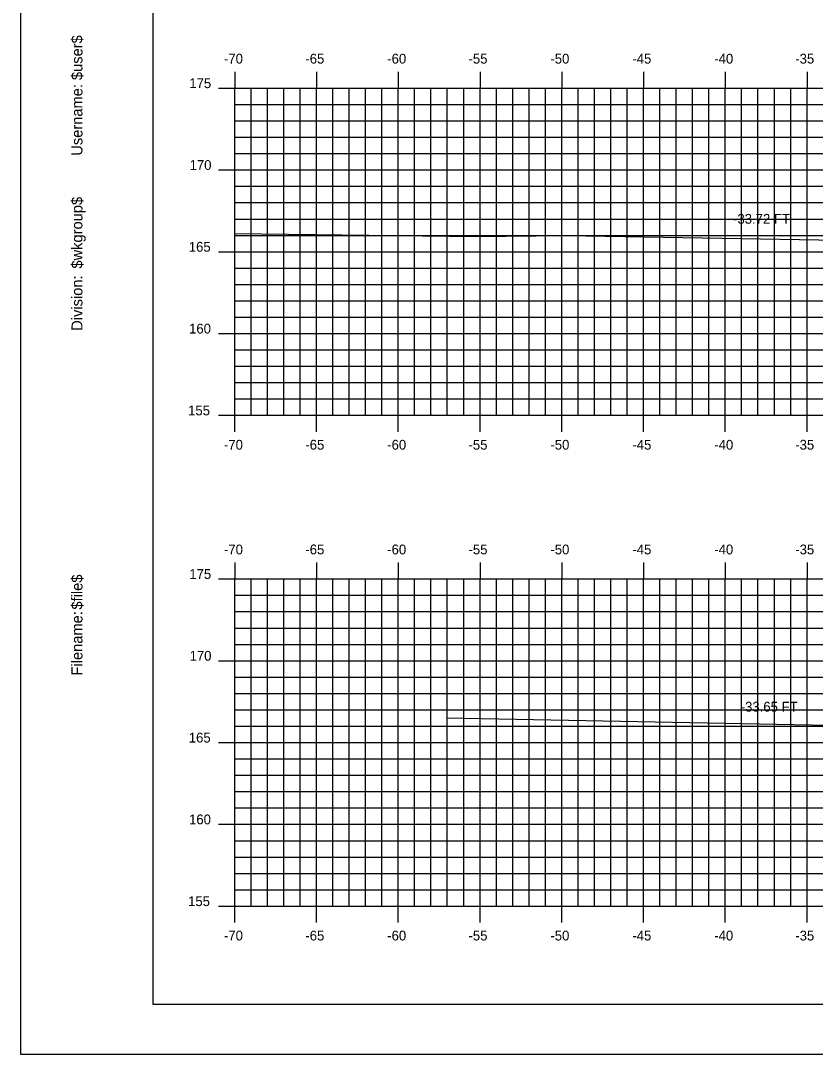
# Model space of a CAD drawing. Extents: x 1142311 to 1142481, y 608981 to 609091.
# Drawn here: x 1142311.2 to 1142359.8, y 608981.3 to 609044.5 of the extents above; entities that cross this region are included whole.
import ezdxf

# ---------------------------------------------------------------- set-up
doc = ezdxf.new("R2010")
doc.units = 0
for name, color, linetype in [('BORDER', 7, 'Continuous'), ('D_Text_Standard', 7, 'Continuous'), ('H_V ANNOTATION', 7, 'Continuous'), ('MAJOR', 7, 'Continuous'), ('MINOR', 7, 'Continuous'), ('PLOT BOUNDARY', 7, 'Continuous'), ('S_Roadway_Centerline', 7, 'Continuous')]:
    doc.layers.add(name, color=color, linetype=linetype)

msp = doc.modelspace()

# ---------------------------------------------------------------- linework, layer by layer
at = {"layer": 'BORDER'}
msp.add_lwpolyline([(1142319.297, 608984.335), (1142479.297, 608984.335), (1142479.297, 609089.335), (1142319.297, 609089.335)], close=True, dxfattribs=at)
at = {"layer": 'MAJOR'}
for p, q in [((1142324.297, 609041.337), (1142324.297, 609040.335)), ((1142329.297, 609041.337), (1142329.297, 609040.335)), ((1142334.297, 609041.337), (1142334.297, 609040.335)), ((1142339.297, 609041.337), (1142339.297, 609040.335)), ((1142344.297, 609041.337), (1142344.297, 609040.335)), ((1142349.297, 609041.337), (1142349.297, 609040.335)), ((1142354.297, 609041.337), (1142354.297, 609040.335)), ((1142359.297, 609041.337), (1142359.297, 609040.335)), ((1142323.295, 609040.335), (1142324.297, 609040.335)), ((1142324.297, 609040.335), (1142464.297, 609040.335)), ((1142324.297, 609020.335), (1142324.297, 609040.335)), ((1142324.297, 609020.335), (1142324.297, 609040.335)), ((1142324.297, 609040.335), (1142464.297, 609040.335)), ((1142329.297, 609020.335), (1142329.297, 609040.335)), ((1142334.297, 609020.335), (1142334.297, 609040.335)), ((1142339.297, 609020.335), (1142339.297, 609040.335)), ((1142344.297, 609020.335), (1142344.297, 609040.335)), ((1142349.297, 609020.335), (1142349.297, 609040.335)), ((1142354.297, 609020.335), (1142354.297, 609040.335)), ((1142359.297, 609020.335), (1142359.297, 609040.335)), ((1142323.295, 609035.335), (1142324.297, 609035.335)), ((1142324.297, 609035.335), (1142464.297, 609035.335)), ((1142323.295, 609030.335), (1142324.297, 609030.335)), ((1142324.297, 609030.335), (1142464.297, 609030.335)), ((1142323.295, 609025.335), (1142324.297, 609025.335)), ((1142324.297, 609025.335), (1142464.297, 609025.335)), ((1142323.295, 609020.335), (1142324.297, 609020.335)), ((1142324.297, 609020.335), (1142464.297, 609020.335)), ((1142324.297, 609020.335), (1142464.297, 609020.335)), ((1142324.297, 609019.333), (1142324.297, 609020.335)), ((1142329.297, 609019.333), (1142329.297, 609020.335)), ((1142334.297, 609019.333), (1142334.297, 609020.335)), ((1142339.297, 609019.333), (1142339.297, 609020.335)), ((1142344.297, 609019.333), (1142344.297, 609020.335)), ((1142349.297, 609019.333), (1142349.297, 609020.335)), ((1142354.297, 609019.333), (1142354.297, 609020.335)), ((1142359.297, 609019.333), (1142359.297, 609020.335)), ((1142324.297, 609011.337), (1142324.297, 609010.335)), ((1142329.297, 609011.337), (1142329.297, 609010.335)), ((1142334.297, 609011.337), (1142334.297, 609010.335)), ((1142339.297, 609011.337), (1142339.297, 609010.335)), ((1142344.297, 609011.337), (1142344.297, 609010.335)), ((1142349.297, 609011.337), (1142349.297, 609010.335)), ((1142354.297, 609011.337), (1142354.297, 609010.335)), ((1142359.297, 609011.337), (1142359.297, 609010.335)), ((1142323.295, 609010.335), (1142324.297, 609010.335)), ((1142324.297, 609010.335), (1142464.297, 609010.335)), ((1142324.297, 608990.335), (1142324.297, 609010.335)), ((1142324.297, 608990.335), (1142324.297, 609010.335)), ((1142324.297, 609010.335), (1142464.297, 609010.335)), ((1142329.297, 608990.335), (1142329.297, 609010.335)), ((1142334.297, 608990.335), (1142334.297, 609010.335)), ((1142339.297, 608990.335), (1142339.297, 609010.335)), ((1142344.297, 608990.335), (1142344.297, 609010.335)), ((1142349.297, 608990.335), (1142349.297, 609010.335)), ((1142354.297, 608990.335), (1142354.297, 609010.335)), ((1142359.297, 608990.335), (1142359.297, 609010.335)), ((1142323.295, 609005.335), (1142324.297, 609005.335)), ((1142324.297, 609005.335), (1142464.297, 609005.335)), ((1142323.295, 609000.335), (1142324.297, 609000.335)), ((1142324.297, 609000.335), (1142464.297, 609000.335)), ((1142323.295, 608995.335), (1142324.297, 608995.335)), ((1142324.297, 608995.335), (1142464.297, 608995.335)), ((1142323.295, 608990.335), (1142324.297, 608990.335)), ((1142324.297, 608990.335), (1142464.297, 608990.335)), ((1142324.297, 608990.335), (1142464.297, 608990.335)), ((1142324.297, 608989.333), (1142324.297, 608990.335)), ((1142329.297, 608989.333), (1142329.297, 608990.335)), ((1142334.297, 608989.333), (1142334.297, 608990.335)), ((1142339.297, 608989.333), (1142339.297, 608990.335)), ((1142344.297, 608989.333), (1142344.297, 608990.335)), ((1142349.297, 608989.333), (1142349.297, 608990.335)), ((1142354.297, 608989.333), (1142354.297, 608990.335)), ((1142359.297, 608989.333), (1142359.297, 608990.335))]:
    msp.add_line(p, q, dxfattribs=at)
at = {"layer": 'MINOR'}
for p, q in [((1142325.297, 609020.335), (1142325.297, 609040.335)), ((1142326.297, 609020.335), (1142326.297, 609040.335)), ((1142327.297, 609020.335), (1142327.297, 609040.335)), ((1142328.297, 609020.335), (1142328.297, 609040.335)), ((1142330.297, 609020.335), (1142330.297, 609040.335)), ((1142331.297, 609020.335), (1142331.297, 609040.335)), ((1142332.297, 609020.335), (1142332.297, 609040.335)), ((1142333.297, 609020.335), (1142333.297, 609040.335)), ((1142335.297, 609020.335), (1142335.297, 609040.335)), ((1142336.297, 609020.335), (1142336.297, 609040.335)), ((1142337.297, 609020.335), (1142337.297, 609040.335)), ((1142338.297, 609020.335), (1142338.297, 609040.335)), ((1142340.297, 609020.335), (1142340.297, 609040.335)), ((1142341.297, 609020.335), (1142341.297, 609040.335)), ((1142342.297, 609020.335), (1142342.297, 609040.335)), ((1142343.297, 609020.335), (1142343.297, 609040.335)), ((1142345.297, 609020.335), (1142345.297, 609040.335)), ((1142346.297, 609020.335), (1142346.297, 609040.335)), ((1142347.297, 609020.335), (1142347.297, 609040.335)), ((1142348.297, 609020.335), (1142348.297, 609040.335)), ((1142350.297, 609020.335), (1142350.297, 609040.335)), ((1142351.297, 609020.335), (1142351.297, 609040.335)), ((1142352.297, 609020.335), (1142352.297, 609040.335)), ((1142353.297, 609020.335), (1142353.297, 609040.335)), ((1142355.297, 609020.335), (1142355.297, 609040.335)), ((1142356.297, 609020.335), (1142356.297, 609040.335)), ((1142357.297, 609020.335), (1142357.297, 609040.335)), ((1142358.297, 609020.335), (1142358.297, 609040.335)), ((1142324.297, 609039.335), (1142464.297, 609039.335)), ((1142324.297, 609039.335), (1142325.299, 609039.335)), ((1142324.297, 609038.335), (1142464.297, 609038.335)), ((1142324.297, 609038.335), (1142325.299, 609038.335)), ((1142324.297, 609037.335), (1142464.297, 609037.335)), ((1142324.297, 609037.335), (1142325.299, 609037.335)), ((1142324.297, 609036.335), (1142464.297, 609036.335)), ((1142324.297, 609036.335), (1142325.299, 609036.335)), ((1142324.297, 609034.335), (1142464.297, 609034.335)), ((1142324.297, 609034.335), (1142325.299, 609034.335)), ((1142324.297, 609033.335), (1142464.297, 609033.335)), ((1142324.297, 609033.335), (1142325.299, 609033.335)), ((1142324.297, 609032.335), (1142464.297, 609032.335)), ((1142324.297, 609032.335), (1142325.299, 609032.335)), ((1142324.297, 609031.335), (1142464.297, 609031.335)), ((1142324.297, 609031.335), (1142325.299, 609031.335)), ((1142324.297, 609029.335), (1142464.297, 609029.335)), ((1142324.297, 609029.335), (1142325.299, 609029.335)), ((1142324.297, 609028.335), (1142464.297, 609028.335)), ((1142324.297, 609028.335), (1142325.299, 609028.335)), ((1142324.297, 609027.335), (1142464.297, 609027.335)), ((1142324.297, 609027.335), (1142325.299, 609027.335)), ((1142324.297, 609026.335), (1142464.297, 609026.335)), ((1142324.297, 609026.335), (1142325.299, 609026.335)), ((1142324.297, 609024.335), (1142464.297, 609024.335)), ((1142324.297, 609024.335), (1142325.299, 609024.335)), ((1142324.297, 609023.335), (1142464.297, 609023.335)), ((1142324.297, 609023.335), (1142325.299, 609023.335)), ((1142324.297, 609022.335), (1142464.297, 609022.335)), ((1142324.297, 609022.335), (1142325.299, 609022.335)), ((1142324.297, 609021.335), (1142464.297, 609021.335)), ((1142324.297, 609021.335), (1142325.299, 609021.335)), ((1142325.297, 608990.335), (1142325.297, 609010.335)), ((1142326.297, 608990.335), (1142326.297, 609010.335)), ((1142327.297, 608990.335), (1142327.297, 609010.335)), ((1142328.297, 608990.335), (1142328.297, 609010.335)), ((1142330.297, 608990.335), (1142330.297, 609010.335)), ((1142331.297, 608990.335), (1142331.297, 609010.335)), ((1142332.297, 608990.335), (1142332.297, 609010.335)), ((1142333.297, 608990.335), (1142333.297, 609010.335)), ((1142335.297, 608990.335), (1142335.297, 609010.335)), ((1142336.297, 608990.335), (1142336.297, 609010.335)), ((1142337.297, 608990.335), (1142337.297, 609010.335)), ((1142338.297, 608990.335), (1142338.297, 609010.335)), ((1142340.297, 608990.335), (1142340.297, 609010.335)), ((1142341.297, 608990.335), (1142341.297, 609010.335)), ((1142342.297, 608990.335), (1142342.297, 609010.335)), ((1142343.297, 608990.335), (1142343.297, 609010.335)), ((1142345.297, 608990.335), (1142345.297, 609010.335)), ((1142346.297, 608990.335), (1142346.297, 609010.335)), ((1142347.297, 608990.335), (1142347.297, 609010.335)), ((1142348.297, 608990.335), (1142348.297, 609010.335)), ((1142350.297, 608990.335), (1142350.297, 609010.335)), ((1142351.297, 608990.335), (1142351.297, 609010.335)), ((1142352.297, 608990.335), (1142352.297, 609010.335)), ((1142353.297, 608990.335), (1142353.297, 609010.335)), ((1142355.297, 608990.335), (1142355.297, 609010.335)), ((1142356.297, 608990.335), (1142356.297, 609010.335)), ((1142357.297, 608990.335), (1142357.297, 609010.335)), ((1142358.297, 608990.335), (1142358.297, 609010.335)), ((1142324.297, 609009.335), (1142464.297, 609009.335)), ((1142324.297, 609009.335), (1142325.299, 609009.335)), ((1142324.297, 609008.335), (1142464.297, 609008.335)), ((1142324.297, 609008.335), (1142325.299, 609008.335)), ((1142324.297, 609007.335), (1142464.297, 609007.335)), ((1142324.297, 609007.335), (1142325.299, 609007.335)), ((1142324.297, 609006.335), (1142464.297, 609006.335)), ((1142324.297, 609006.335), (1142325.299, 609006.335)), ((1142324.297, 609004.335), (1142464.297, 609004.335)), ((1142324.297, 609004.335), (1142325.299, 609004.335)), ((1142324.297, 609003.335), (1142464.297, 609003.335)), ((1142324.297, 609003.335), (1142325.299, 609003.335)), ((1142324.297, 609002.335), (1142464.297, 609002.335)), ((1142324.297, 609002.335), (1142325.299, 609002.335)), ((1142324.297, 609001.335), (1142464.297, 609001.335)), ((1142324.297, 609001.335), (1142325.299, 609001.335)), ((1142324.297, 608999.335), (1142464.297, 608999.335)), ((1142324.297, 608999.335), (1142325.299, 608999.335)), ((1142324.297, 608998.335), (1142464.297, 608998.335)), ((1142324.297, 608998.335), (1142325.299, 608998.335)), ((1142324.297, 608997.335), (1142464.297, 608997.335)), ((1142324.297, 608997.335), (1142325.299, 608997.335)), ((1142324.297, 608996.335), (1142464.297, 608996.335)), ((1142324.297, 608996.335), (1142325.299, 608996.335)), ((1142324.297, 608994.335), (1142464.297, 608994.335)), ((1142324.297, 608994.335), (1142325.299, 608994.335)), ((1142324.297, 608993.335), (1142464.297, 608993.335)), ((1142324.297, 608993.335), (1142325.299, 608993.335)), ((1142324.297, 608992.335), (1142464.297, 608992.335)), ((1142324.297, 608992.335), (1142325.299, 608992.335)), ((1142324.297, 608991.335), (1142464.297, 608991.335)), ((1142324.297, 608991.335), (1142325.299, 608991.335))]:
    msp.add_line(p, q, dxfattribs=at)
at = {"layer": 'PLOT BOUNDARY'}
msp.add_lwpolyline([(1142311.204, 608981.276), (1142481.204, 608981.276), (1142481.204, 609091.276), (1142311.204, 609091.276)], close=True, dxfattribs=at)
at = {"layer": 'S_Roadway_Centerline'}
for points in [[(1142324.297, 609031.45), (1142339.038, 609031.267), (1142344.584, 609031.334), (1142365.956, 609030.965), (1142367.521, 609030.805), (1142367.992, 609030.755), (1142371.922, 609030.416), (1142372.533, 609030.575), (1142376.384, 609031.552), (1142376.966, 609031.616), (1142379.377, 609031.848), (1142381.17, 609031.866), (1142390.341, 609031.991), (1142392.202, 609031.893), (1142401.531, 609031.422), (1142402.162, 609031.372), (1142406.958, 609030.794), (1142410.108, 609030.213), (1142410.523, 609030.158), (1142411.1, 609030.269), (1142416.795, 609030.647), (1142419.825, 609030.564), (1142444.36, 609030.432), (1142450.84, 609030.42)], [(1142337.275, 609001.841), (1142365.933, 609001.298), (1142368.833, 609001.283), (1142372.333, 609000.894), (1142372.884, 609000.81), (1142375.622, 609001.579), (1142376.038, 609001.669), (1142379.479, 609002.185), (1142379.698, 609002.212), (1142380.725, 609002.225), (1142390.691, 609002.337), (1142391.949, 609002.296), (1142402.095, 609001.847), (1142402.522, 609001.826), (1142406.399, 609001.303), (1142409.823, 609000.49), (1142410.322, 609000.387), (1142415.334, 609002.008), (1142415.882, 609002.14), (1142421.695, 609001.98), (1142453.493, 609001.317)]]:
    msp.add_lwpolyline(points, dxfattribs=at)

# ---------------------------------------------------------------- texts
at = {"layer": 'BORDER'}
for s, p in [('$user$', (1142314.982, 609040.827)), ('Username:', (1142314.982, 609036.203)), ('$wkgroup$', (1142314.982, 609029.305)), ('Division:', (1142314.982, 609025.501)), ('$file$', (1142314.982, 609008.461)), ('Filename:', (1142314.982, 609004.433))]:
    msp.add_text(s, height=0.6696, rotation=90, dxfattribs=at).set_placement(p)
at = {"layer": 'D_Text_Standard'}
for s, p in [('-33.72 FT', (1142354.771, 609032.046)), ('-33.65 FT', (1142355.241, 609002.223))]:
    msp.add_text(s, height=0.6, dxfattribs=at).set_placement(p)
at = {"layer": 'H_V ANNOTATION'}
for s, p in [('-70', (1142323.638, 609041.835)), ('-65', (1142328.615, 609041.835)), ('-60', (1142333.623, 609041.835)), ('-55', (1142338.593, 609041.835)), ('-50', (1142343.601, 609041.835)), ('-45', (1142348.615, 609041.835)), ('-40', (1142353.623, 609041.835)), ('-35', (1142358.577, 609041.835)), ('175', (1142321.518, 609040.335)), ('170', (1142321.534, 609035.335)), ('165', (1142321.486, 609030.335)), ('160', (1142321.502, 609025.335)), ('155', (1142321.443, 609020.335)), ('-70', (1142323.638, 609018.235)), ('-65', (1142328.615, 609018.235)), ('-60', (1142333.623, 609018.235)), ('-55', (1142338.593, 609018.235)), ('-50', (1142343.601, 609018.235)), ('-45', (1142348.615, 609018.235)), ('-40', (1142353.623, 609018.235)), ('-35', (1142358.577, 609018.235)), ('-70', (1142323.638, 609011.835)), ('-65', (1142328.615, 609011.835)), ('-60', (1142333.623, 609011.835)), ('-55', (1142338.593, 609011.835)), ('-50', (1142343.601, 609011.835)), ('-45', (1142348.615, 609011.835)), ('-40', (1142353.623, 609011.835)), ('-35', (1142358.577, 609011.835)), ('175', (1142321.518, 609010.335)), ('170', (1142321.534, 609005.335)), ('165', (1142321.486, 609000.335)), ('160', (1142321.502, 608995.335)), ('155', (1142321.443, 608990.335)), ('-70', (1142323.638, 608988.235)), ('-65', (1142328.615, 608988.235)), ('-60', (1142333.623, 608988.235)), ('-55', (1142338.593, 608988.235)), ('-50', (1142343.601, 608988.235)), ('-45', (1142348.615, 608988.235)), ('-40', (1142353.623, 608988.235)), ('-35', (1142358.577, 608988.235))]:
    msp.add_text(s, height=0.6, dxfattribs=at).set_placement(p)
at = {"layer": 'MAJOR'}
for p in [(1142324.292, 609020.335), (1142324.292, 608990.335)]:
    msp.add_text('-', height=0.006, dxfattribs=at).set_placement(p)

doc.saveas('drawing.dxf')
